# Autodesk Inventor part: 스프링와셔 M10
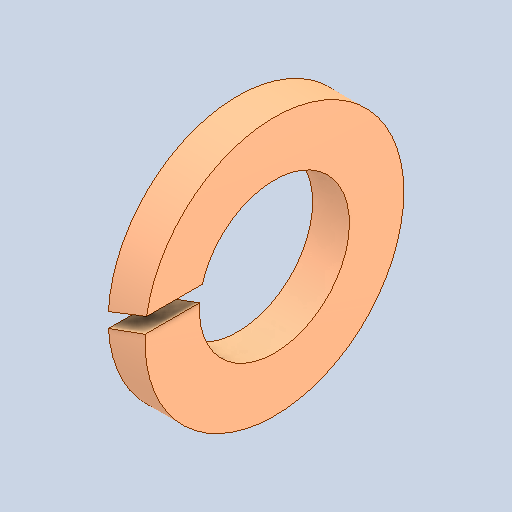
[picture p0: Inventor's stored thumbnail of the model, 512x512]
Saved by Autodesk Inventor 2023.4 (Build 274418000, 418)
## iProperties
Created: 2024-09
Part Number: 스프링와셔 M10
Material: 강철, 연강
Description: 스프링 잠금 와셔
Document SubType Name: Modeling
Designer: EDU
Density: 7.85 g/cm^3
Appearance: 기본값
Author: jhkim
Sending System: Autodesk Inventor 2025
Preprocessor: ST-DEVELOPER v20
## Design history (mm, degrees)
feature "Solid1"
node "솔리드1"
